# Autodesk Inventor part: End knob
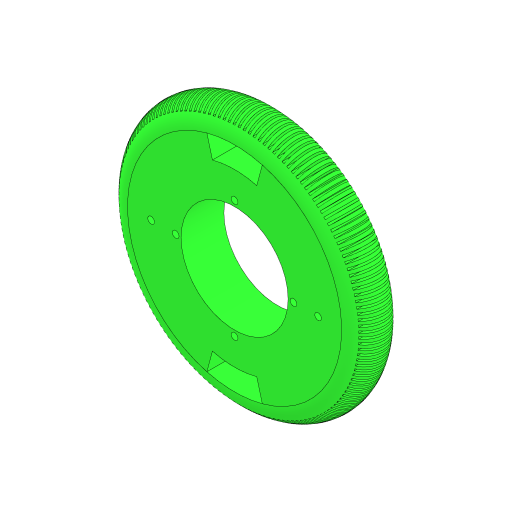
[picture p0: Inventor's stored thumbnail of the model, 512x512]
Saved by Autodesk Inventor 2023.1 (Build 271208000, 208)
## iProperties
Created: 2020-01
Part Number: End knob
Material: Generic
Document SubType Name: Modeling
Designer: ftrauzettel
Density: 1 g/cm^3
Appearance: Default
Sending System: SolidWorks 2016
Last Author: Pam
Last Saved: 2020-02-24
Author: ftrauzettel
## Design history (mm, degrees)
feature "CirPattern1"
body "Solid1"
